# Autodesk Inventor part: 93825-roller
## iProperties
Author: Administrator
Shininess: 64.0
Angle Display Precision: 2
Document Length Units: 11272
Document Angle Units: 11286
Document Time Units: 11279
Document Mass Units: 11290
Document Length Units Precision: 3
Document Angle Units Precision: 2
Compacted: True
PropertySet Name: _Private Model Information
Created: 2002-03
Part Number: 93825-roller
Material: Stainless Steel, 440C
Document SubType Name: Modeling
Designer: Administrator
Control State: 0
Master: False
Checked Out: False
PropertySet Name: Design Tracking Control
Density: 0.0
Volumn: 0.0
Area: 0.0
PropertySet Name: Model Information
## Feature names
1. Revolution1
